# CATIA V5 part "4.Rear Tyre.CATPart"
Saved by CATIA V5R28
Part number: Rear tyre
Bounding box of the stored display mesh (mm): x -44.5 to 44.5, y -196 to 196, z -196 to 196
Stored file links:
  D:\Catia Cycle design\4.Rear Tyre.CATPart
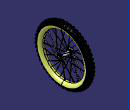
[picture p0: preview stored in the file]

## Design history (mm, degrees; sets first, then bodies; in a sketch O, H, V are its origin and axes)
Set1
  Sketch1 on zx-plane, origin (0, 0, 0), H (-1, 0, 0), V (0, 0, 1)
    construction line L1 (0, 0) -> (0, 170)
    arc A1 centre (0, 170) radius 22 from (22, 170) to (-22, 170) ccw
    point P2 (-22, 170)
    point P3 (22, 170)
    arc A2 centre (-23, 170) radius 1 from (-22, 170) to (-24, 170) ccw
    point P4 (-23, 170)
    point P5 (-24, 170)
    axis line L2 (22, 170) -> (-22, 170)
    point P6 (24, 170)
    point P7 (22, 170)
    arc A3 centre (23, 170) radius 1 from (22, 170) to (24, 170) cw
    arc A4 centre (0, 170) radius 24 from (-24, 170) to (-6.8557, 147) ccw
    point P9 (-24, 170)
    line L3 (-6.8557, 147) -> (6.8557, 147)
    point P11 (6.8557, 147)
    arc A5 centre (0, 170) radius 24 from (6.8557, 147) to (24, 170) ccw
    length L1 = 170
    radius A1 = 22
    radius A2 = 1
    distance L2 L3 = 23
    vertical: L1 V
    tangency: A2 A1, A4 A3, A4 A2, A3 A1
    horizontal: L2 H, L3 H
    coincidence: P5 L2, P4 L2, P9 L2, P11 A4, A4 A5, P3 P7, P5 P9
    symmetry: P5 P6 L1, P2 P7 L1, A2 A3 L1
  Plane1: type Offset, RefPlane xy-plane, Offset 149
  Plane2: type Offset, RefPlane zx-plane, Offset 149
  Point1: type Center, Curve Sketch7
  Point2: (34.5, -14.6239, 3.3378)
  Line1: type PtDir, RefPoint Point2, Direction (1, 0, 0), Start 0, End 8
  Line2: type PtPt, FirstPoint Point1, SecondPoint Point2
  Corner1: Element1 Line2, Element2 Line1, Radius 3
  Point3: type Center, Curve Sketch8
  Point4: (-34.5, 6.5083, 13.5145)
  Line3: type PtDir, RefPoint Point4, Direction (1, 0, 0), Start 0, End 8
  Line4: type PtPt, FirstPoint Point4, SecondPoint Point3
  Corner2: Element1 Line4, Element2 Line3, Radius 3
  Plane3: type Offset, RefPlane xy-plane, Offset 197
Body1 (main body)
  Shaft1: profile Sketch1, axis X axis, angle 360
  Sketch2 on yz-plane, origin (0, 0, 0), H (0, 1, 0), V (0, 0, 1)
    circle A1 centre (0, 0) radius 8.8
    circle A2 centre (0, 0) radius 5
    radius A1 = 8.8
    radius A2 = 5
  Pad1: profile Sketch2, direction (1, 0, 0), length 38.5, mirrored extent
  Sketch3 on start face of Pad1, origin (-38.5, 0, 0), H (0, -1, 0), V (0, 0, 1)
    circle A1 centre (0, 0) radius 11.5
    projected circle E1 centre (0, 0) radius 8.8 from edge [start face of Pad1 | face of Pad1 from Sketch2.A1]
    radius A1 = 11.5
  Pad2: profile Sketch3, direction (1, 0, 0), length 4
  Sketch4 on end face of Pad2, origin (-34.5, 0, 0), H (0, 1, 0), V (0, 0, 1)
    circle A1 centre (0, 0) radius 10
    radius A1 = 10
  Pad3: profile Sketch4, direction (1, 0, 0), length 4
  Mirror1: of the body so far, about yz-plane
  Fillet1: radius 1, on edge [face of Mirror1 | face of Mirror1]
  Fillet2: radius 1, on edge [end face of Pad2 | face of Pad3 from Sketch4.A1]
  Sketch5 on face of Mirror1, origin (30.5, 0, 0), H (0, -1, 0), V (0, 0, 1)
    circle A1 centre (0, 0) radius 19
    point P1 (0, 0)
    projected circle E1 centre (0, 0) radius 8.8 from edge [face of Mirror1 | face of Mirror1]
    radius A1 = 19
    coincidence: P1 H, P1 O
  Pad4: profile Sketch5, direction (-1, 0, 0), length 3
  Sketch6 on start face of Pad4, origin (30.5, 0, 0), H (0, 1, 0), V (0, 0, 1)
    circle A1 centre (0, 15) radius 1.5
    point P1 (0, 15)
    radius A1 = 1.5
    distance H P1 = 15
    coincidence: P1 V
  Pocket1: profile Sketch6, direction (-1, 0, 0), through (limit type 3)
  CircPattern1: of Pocket1, instances 14, angular step 25.7143 {= 360.0*1 deg/CircPattern1.AngularNumber}, axis from X axis
  Mirror2: of the body so far, about yz-plane
  Sketch7 on Plane1, origin (0, 0, 149), H (1, 0, 0), V (0, 1, 0)
    circle A1 centre (0, 0) radius 1.5
    point P1 (1.5, 0)
    radius A1 = 1.5
    coincidence: A1 P1, P1 H
  Pocket2: profile Sketch7, direction (0, 0, -1), length 5
  Rib1: profile Sketch7, centre curve Corner1
  CircPattern2: of Pocket2, instances 28, angular step 12.8571 {= 360.0*1 deg/CircPattern2.AngularNumber}, axis from X axis
  CircPattern3: of Rib1, instances 14, angular step 25.7143 {= 360.0*1 deg/CircPattern3.AngularNumber}, axis from X axis
  Sketch8 on Plane2, origin (0, 149, 0), H (-1, 0, 0), V (0, 0, 1)
    projected circle E1 centre (0, 0) radius 1.5 from edge [face of CircPattern2 | face of Mirror2]
  Rib2: profile Sketch8, centre curve Corner2
  CircPattern4: of Rib2, instances 14, angular step 25.7143 {= 360.0*1 deg/CircPattern4.AngularNumber}, axis from X axis
  Sketch9 on face of Mirror2, origin (38.5, 0, 0), H (0, 1, 0), V (0, 0, 1)
    circle A1 centre (0, 0) radius 7
    projected circle E1 centre (0, 0) radius 5 from edge [face of Mirror2 | face of Mirror2]
    radius A1 = 7
  Pad5: profile Sketch9, direction (1, 0, 0), length 6
  Sketch10 on Plane3, origin (0, 0, 197), H (1, 0, 0), V (0, 1, 0)
    point P1 (-4, 0)
    line L1 (-4, 0) -> (4, 0)
    line L2 (4, 0) -> (4, 12)
    line L3 (4, 12) -> (-4, 12)
    line L4 (-4, 12) -> (-4, 0)
    point P5 (-16, 6)
    line L5 (-16, 6) -> (-16, -6)
    point P6 (-16, -6)
    line L6 (-16, -6) -> (-10, -3)
    point P7 (-10, -3)
    line L7 (-10, -3) -> (-10, 3)
    point P8 (-10, 3)
    line L8 (-10, 3) -> (-16, 6)
    reference projected point E1 (0, 0) from edge
    point P9 (16, -6)
    point P10 (16, 6)
    line L9 (16, 6) -> (16, -6)
    point P11 (10, 3)
    line L10 (10, 3) -> (16, 6)
    point P12 (10, -3)
    line L11 (10, -3) -> (10, 3)
    line L12 (16, -6) -> (10, -3)
    distance L4 L2 = 8
    distance L3 L1 = 12
    length L5 = 12
    length L7 = 6
    distance L5 L7 = 6
    distance E1 L7 = 10
    coincidence: P1 H
    horizontal: L1 H, L3 H
    vertical: L2 V, L4 V, L5 V, L7 V
    symmetry: L4 L2 V, P7 P8 H, P6 P5 H, P6 P9 V, P5 P10 V, L5 L9 V, P8 P11 V, L8 L10 V, P7 P12 V, L7 L11 V, L6 L12 V
  Pad6: profile Sketch10, direction (0, 0, 1), up to the existing solid (limit type 2)
  CircPattern5: of Pad6, instances 50, angular step 7.2, axis from X axis
  Sketch11 on zx-plane, origin (0, 0, 0), H (-1, 0, 0), V (0, 0, 1)
    arc A1 centre (0, 171) radius 25 from (25, 171) to (-24.9983, 170.7064) ccw
    point P1 (0, 171)
    reference projected line E1 (-4, 197) -> (4, 197) from edge [face of Pad6 from Sketch10.L3 | start face of Pad6]
    line L1 (-24.9983, 170.7064) -> (-25.5629, 218.7841)
    line L2 (-25.5629, 218.7841) -> (25, 218.7841)
    line L3 (25, 218.7841) -> (25, 171)
    radius A1 = 25
    distance A1 E1 = 1
    coincidence: P1 V
    tangency: L1 A1
    horizontal: L2 H
    vertical: L3 V
  Groove1: profile Sketch11, axis X axis, angle 360
  Mirror3: of Pad5, about yz-plane
  Sketch12 on face of Mirror2, origin (-38.5, 0, 0), H (0, -1, 0), V (0, 0, 1)
    circle A1 centre (0, 0) radius 29.4
    projected circle E1 centre (0, 0) radius 5 from edge [face of Mirror3 | face of Mirror3]
    radius A1 = 29.4
  Pad7: profile Sketch12, direction (-1, 0, 0), length 2
  Sketch13 on end face of Pad7, origin (-40.5, 0, 0), H (0, -1, 0), V (0, 0, 1)
    circle A1 centre (0, 29.4) radius 5
    point P1 (0, 29.4)
    reference projected circle E1 centre (0, 0) radius 29.4 from edge [face of Pad7 from Sketch12.A1 | end face of Pad7]
    radius A1 = 5
    coincidence: P1 V, P1 E1
  Pocket3: profile Sketch13, direction (1, 0, 0), length 2
  CircPattern6: of Pocket3, instances 15, angular step 24 {= 360.0*1 deg/CircPattern6.AngularNumber}, axis from X axis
